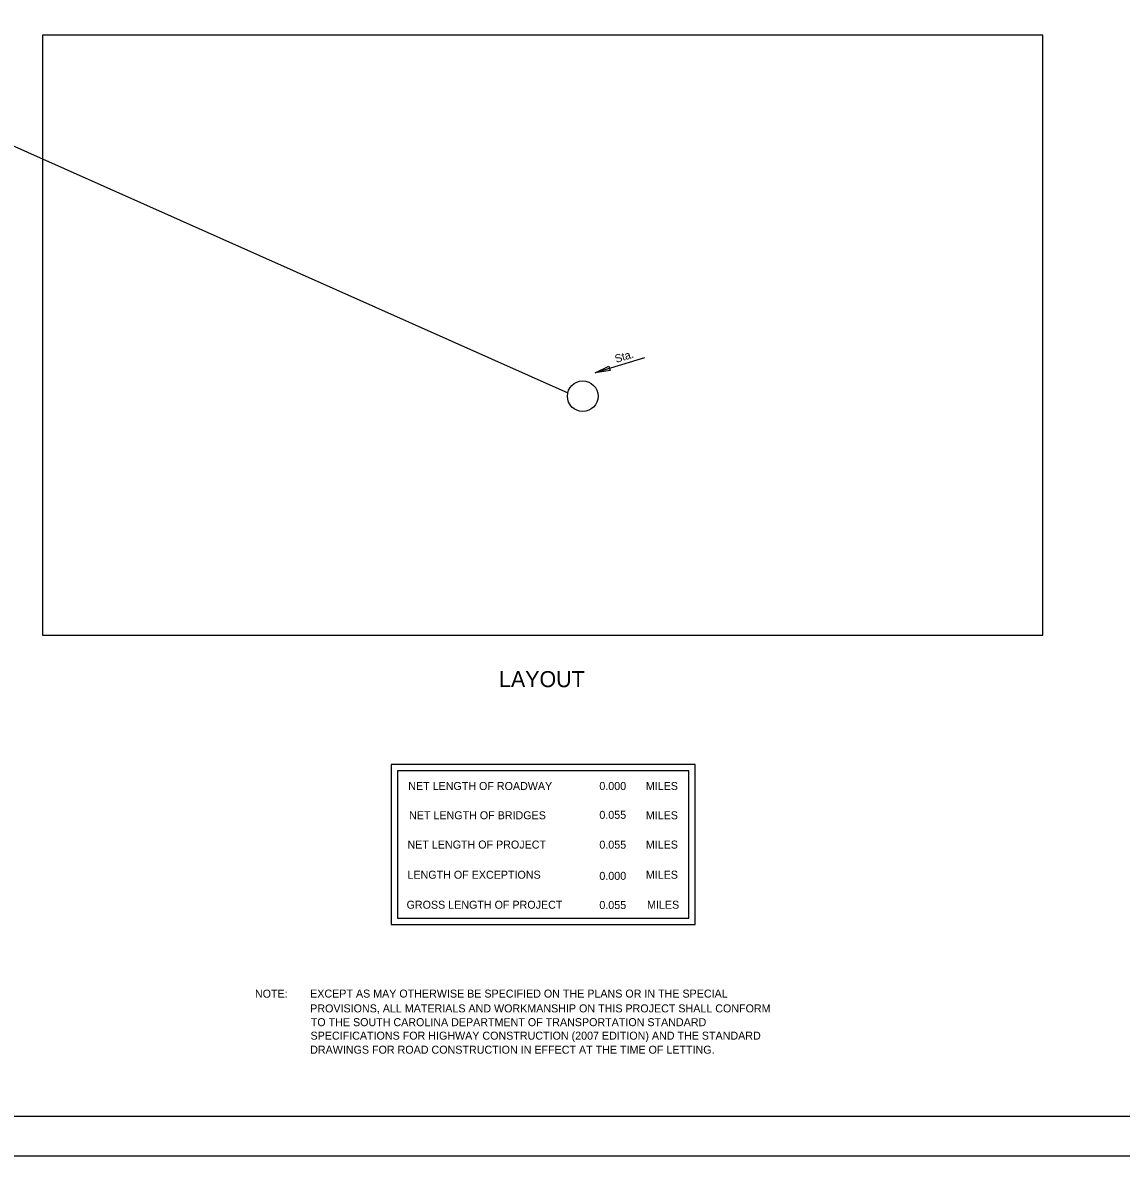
# Model space of a CAD drawing. Extents: x 140 to 1940, y 64 to 1307.
# Drawn here: x 752 to 1438, y 64 to 772 of the extents above; entities that cross this region are included whole.
import ezdxf

# ---------------------------------------------------------------- set-up
doc = ezdxf.new("R2010")
doc.units = 0
for name, color, linetype in [('BR_BORDER LINES', 7, 'Continuous'), ('BR_DETAILS', 7, 'Continuous'), ('BR_REBAR', 7, 'Continuous'), ('BR_TABLE LINES', 7, 'Continuous'), ('BR_TEXT', 7, 'Continuous'), ('Default', 7, 'Continuous'), ('GN_TitleSheetMap', 7, 'Continuous'), ('RD_SHT_IplotShp', 7, 'Continuous')]:
    doc.layers.add(name, color=color, linetype=linetype)

msp = doc.modelspace()

# ---------------------------------------------------------------- linework, layer by layer
at = {"layer": 'BR_BORDER LINES'}
msp.add_line((239.58, 88.98), (1914.58, 88.98), dxfattribs=at)
at = {"layer": 'BR_REBAR'}
msp.add_line((1140.35, 562.99), (1109.5, 553.5), dxfattribs=at)
msp.add_lwpolyline([(1118.88, 554.91), (1109.5, 553.5), (1118.05, 557.6)], close=True, dxfattribs=at)
at = {"layer": 'BR_TABLE LINES'}
msp.add_lwpolyline([(684.21, 702.54), (730.01, 702.54), (1092.4, 540.92)], dxfattribs=at)
msp.add_circle((1101.74, 538.92), 9.55, dxfattribs=at)
at = {"layer": 'Default'}
for points in [[(1172.02, 308.75), (982.02, 308.75), (982.02, 208.75), (1172.02, 208.75)], [(1168.02, 304.75), (986.02, 304.75), (986.02, 212.75), (1168.02, 212.75)]]:
    msp.add_lwpolyline(points, close=True, dxfattribs=at)
at = {"layer": 'GN_TitleSheetMap'}
msp.add_lwpolyline([(764.25, 389.5), (1389.25, 389.5), (1389.25, 764.5), (764.25, 764.5)], close=True, dxfattribs=at)
at = {"layer": 'RD_SHT_IplotShp'}
msp.add_lwpolyline([(139.58, 1163.91), (1939.58, 1163.91), (1939.58, 63.91), (139.58, 63.91)], close=True, dxfattribs=at)

# ---------------------------------------------------------------- texts
at = {"layer": 'BR_DETAILS'}
for s, height, p in [('LAYOUT', 10, (1049.48, 357.12)), ('NOTE:', 5, (897.01, 163.05)), ('EXCEPT AS MAY OTHERWISE BE SPECIFIED ON THE PLANS OR IN THE SPECIAL ', 5.0001, (931.47, 163.1)), ('PROVISIONS, ALL MATERIALS AND WORKMANSHIP ON THIS PROJECT SHALL CONFORM ', 5.0001, (931.52, 153.85)), ('TO THE SOUTH CAROLINA DEPARTMENT OF TRANSPORTATION STANDARD ', 5.0001, (931.88, 145.24)), ('SPECIFICATIONS FOR HIGHWAY CONSTRUCTION (2007 EDITION) AND THE STANDARD', 5.0001, (931.72, 136.81)), ('DRAWINGS FOR ROAD CONSTRUCTION IN EFFECT AT THE TIME OF LETTING.', 5.0001, (931.5, 128.04))]:
    msp.add_text(s, height=height, dxfattribs=at).set_placement(p)
at = {"layer": 'BR_TEXT'}
for s, p in [('0.000', (1112.14, 292.83)), ('0.055', (1112.14, 274.81)), ('0.055', (1112.14, 256.16)), ('0.000', (1112.14, 236.68)), ('0.055', (1112.14, 218.46))]:
    msp.add_text(s, height=5, dxfattribs=at).set_placement(p)
at = {"layer": 'Default'}
msp.add_text('Sta.', height=5, rotation=17.09511, dxfattribs=at).set_placement((1122.66, 559.68))
for s, p in [('NET LENGTH OF ROADWAY', (992.77, 292.83)), ('MILES', (1141.17, 292.83)), ('NET LENGTH OF BRIDGES', (993.27, 274.53)), ('MILES', (1141.16, 274.53)), ('NET LENGTH OF PROJECT', (992.27, 256.23)), ('MILES', (1141.15, 256.23)), ('LENGTH OF EXCEPTIONS', (992.27, 237.38)), ('MILES', (1141.17, 237.38)), ('GROSS LENGTH OF PROJECT', (991.72, 218.63)), ('MILES', (1141.92, 218.63))]:
    msp.add_text(s, height=5, dxfattribs=at).set_placement(p)

doc.saveas('drawing.dxf')
